Omron CX-Programmer project NuevoProyecto (CX-Programmer 9.50)

# PLC NewPLC1: CQM1 CPU21

## Program P20_1b2 (no task)
Local symbols
A 0.04 BOOL  ; Selección tolva A
B 0.05 BOOL  ; Selección tolva B
De 0.07 BOOL  ; Selección CIN3 derecha
EVA 100.04 BOOL  ; Electroválvula tolva A
EVB 100.05 BOOL  ; Electroválvula tolva B
Em 15.00 BOOL  ; Emergencia memorizada
Etapa_0 10.00 BOOL
Etapa_1 10.01 BOOL
Etapa_10 10.08 BOOL
Etapa_11 10.09 BOOL
Etapa_12 10.10 BOOL
Etapa_13 10.11 BOOL
Etapa_14 10.12 BOOL
Etapa_2 10.02 BOOL
Etapa_3 10.03 BOOL
Etapa_4 10.04 BOOL
Etapa_5 10.05 BOOL
Etapa_6 10.06 BOOL
Etapa_7 10.07 BOOL
FS_Etapa_12 15.07 BOOL  ; Flanco de subida Etapa_12
FS_Etapa_2 15.03 BOOL  ; Flanco de subida Etapa_2
FS_Etapa_3 15.04 BOOL  ; Flanco de subida Etapa_3
FS_Etapa_6 15.05 BOOL  ; Flanco de subida Etapa_6
FS_Etapa_7 15.06 BOOL  ; Flanco de subida Etapa_7
H_1 100.06 BOOL  ; Lámpara marcha
H_2 100.07 BOOL  ; Lámpara paro
H_3 101.00 BOOL  ; Lámpara emergencia
H_4 101.01 BOOL  ; Lámpara RT1
H_5 101.02 BOOL  ; Lámpara RT2
H_6 101.03 BOOL  ; Lámpara RT3
Iz 0.06 BOOL  ; Selección CIN3 izquierda
K1 100.00 BOOL  ; Contactor CIN1
K2 100.01 BOOL  ; Contactor CIN2
K3D 100.03 BOOL  ; Contactor derecha CIN3
K3I 100.02 BOOL  ; Contactor izquierda CIN3
PE 0.02 BOOL  ; Pulsador de emergencia
PM 0.00 BOOL  ; Pulsador de marcha
PP 0.01 BOOL  ; Pulsador de paro
PR 0.03 BOOL  ; Pulsador de rearme
RT 15.01 BOOL  ; RT=RT1+RT2+RT3
RT1 0.08 BOOL  ; Relé térmico CIN1
RT2 0.09 BOOL  ; Relé térmico CIN2
RT3 0.10 BOOL  ; Relé térmico CIN3
RTm 15.02 BOOL  ; Relés térmicos memorizados
T_0 15.03 BOOL  ; Variable auxiliar T_0

### Section Sección1_Programa_principal
; Etapas 0 ... 7

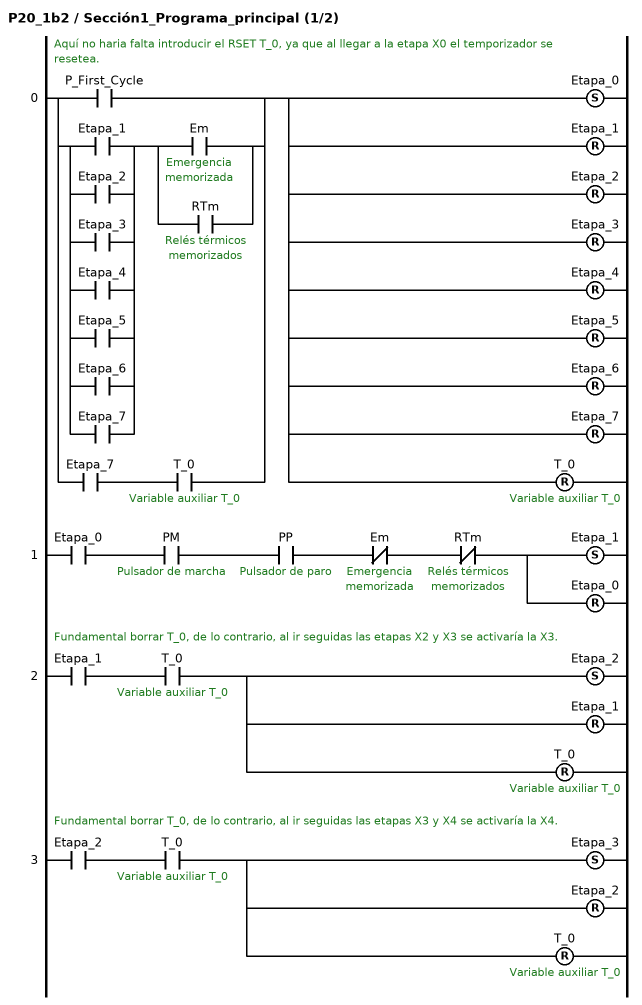
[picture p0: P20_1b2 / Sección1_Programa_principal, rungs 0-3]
; rung 0: Aquí no haria falta introducir el RSET T_0, ya que al llegar a la etapa X0 el temporizador se resetea.
LD P_First_Cycle
LD Etapa_1
OR Etapa_2
OR Etapa_3
OR Etapa_4
OR Etapa_5
OR Etapa_6
OR Etapa_7
LD Em  ; Emergencia memorizada
OR RTm  ; Relés térmicos memorizados
ANDLD
ORLD
LD Etapa_7
AND T_0  ; Variable auxiliar T_0
ORLD
SET Etapa_0
RSET Etapa_1
RSET Etapa_2
RSET Etapa_3
RSET Etapa_4
RSET Etapa_5
RSET Etapa_6
RSET Etapa_7
RSET T_0  ; Variable auxiliar T_0  // Como norma general se reseteará la variable auxiliar T_0 nada más haya cumplido su cometido.
; rung 1
LD Etapa_0
AND PM  ; Pulsador de marcha
AND PP  ; Pulsador de paro
ANDNOT Em  ; Emergencia memorizada
ANDNOT RTm  ; Relés térmicos memorizados
SET Etapa_1
RSET Etapa_0
; rung 2: Fundamental borrar T_0, de lo contrario, al ir seguidas las etapas X2 y X3 se activaría la X3.
LD Etapa_1
AND T_0  ; Variable auxiliar T_0
SET Etapa_2
RSET Etapa_1
RSET T_0  ; Variable auxiliar T_0  // Como norma general se reseteará la variable auxiliar T_0 nada más haya cumplido su cometido.
; rung 3: Fundamental borrar T_0, de lo contrario, al ir seguidas las etapas X3 y X4 se activaría la X4.
LD Etapa_2
AND T_0  ; Variable auxiliar T_0
SET Etapa_3
RSET Etapa_2
RSET T_0  ; Variable auxiliar T_0  // Como norma general se reseteará la variable auxiliar T_0 nada más haya cumplido su cometido.

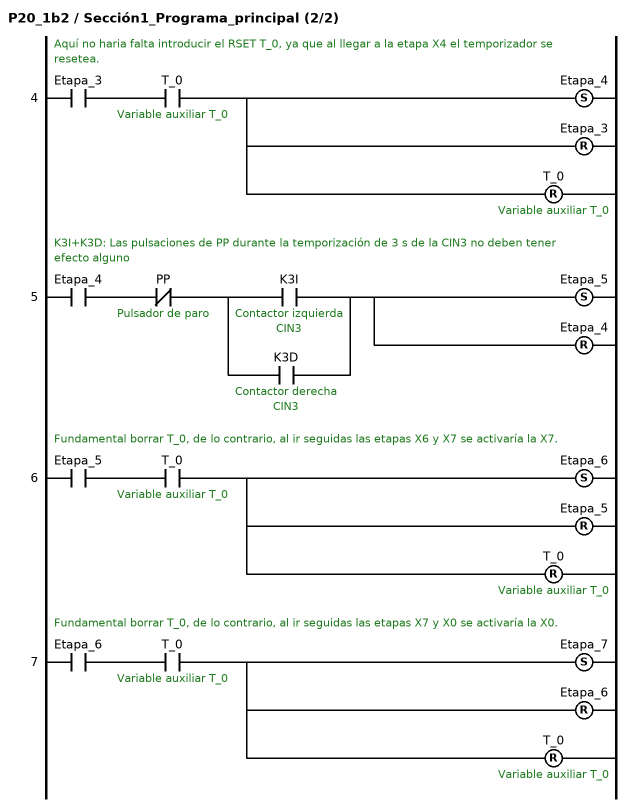
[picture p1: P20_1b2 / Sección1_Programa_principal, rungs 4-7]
; rung 4: Aquí no haria falta introducir el RSET T_0, ya que al llegar a la etapa X4 el temporizador se resetea.
LD Etapa_3
AND T_0  ; Variable auxiliar T_0
SET Etapa_4
RSET Etapa_3
RSET T_0  ; Variable auxiliar T_0  // Como norma general se reseteará la variable auxiliar T_0 nada más haya cumplido su cometido.
; rung 5: K3I+K3D: Las pulsaciones de PP durante la temporización de 3 s de la CIN3 no deben tener efecto alguno
LD Etapa_4
ANDNOT PP  ; Pulsador de paro
LD K3I  ; Contactor izquierda CIN3
OR K3D  ; Contactor derecha CIN3
ANDLD
SET Etapa_5
RSET Etapa_4
; rung 6: Fundamental borrar T_0, de lo contrario, al ir seguidas las etapas X6 y X7 se activaría la X7.
LD Etapa_5
AND T_0  ; Variable auxiliar T_0
SET Etapa_6
RSET Etapa_5
RSET T_0  ; Variable auxiliar T_0
; rung 7: Fundamental borrar T_0, de lo contrario, al ir seguidas las etapas X7 y X0 se activaría la X0.
LD Etapa_6
AND T_0  ; Variable auxiliar T_0
SET Etapa_7
RSET Etapa_6
RSET T_0  ; Variable auxiliar T_0

### Section Sección2_Disparo_térmicos
; Etapas 10 ... 14

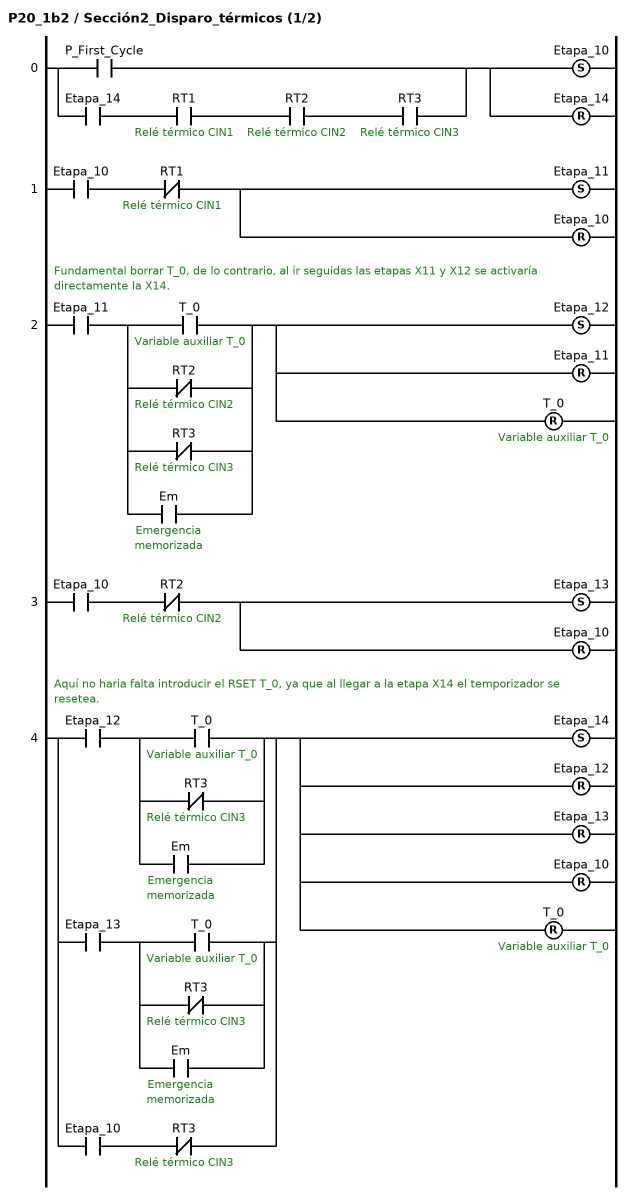
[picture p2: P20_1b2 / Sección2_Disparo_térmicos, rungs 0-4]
; rung 0
LD P_First_Cycle
LD Etapa_14
AND RT1  ; Relé térmico CIN1
AND RT2  ; Relé térmico CIN2
AND RT3  ; Relé térmico CIN3
ORLD
SET Etapa_10
RSET Etapa_14
; rung 1
LD Etapa_10
ANDNOT RT1  ; Relé térmico CIN1
SET Etapa_11
RSET Etapa_10
; rung 2: Fundamental borrar T_0, de lo contrario, al ir seguidas las etapas X11 y X12 se activaría directamente la X14.
LD Etapa_11
LD T_0  ; Variable auxiliar T_0
ORNOT RT2  ; Relé térmico CIN2
ORNOT RT3  ; Relé térmico CIN3
OR Em  ; Emergencia memorizada
ANDLD
SET Etapa_12
RSET Etapa_11
RSET T_0  ; Variable auxiliar T_0
; rung 3
LD Etapa_10
ANDNOT RT2  ; Relé térmico CIN2
SET Etapa_13
RSET Etapa_10
; rung 4: Aquí no haria falta introducir el RSET T_0, ya que al llegar a la etapa X14 el temporizador se resetea.
LD Etapa_12
LD T_0  ; Variable auxiliar T_0
ORNOT RT3  ; Relé térmico CIN3
OR Em  ; Emergencia memorizada
ANDLD
LD Etapa_13
LD T_0  ; Variable auxiliar T_0
ORNOT RT3  ; Relé térmico CIN3
OR Em  ; Emergencia memorizada
ANDLD
ORLD
LD Etapa_10
ANDNOT RT3  ; Relé térmico CIN3
ORLD
SET Etapa_14
RSET Etapa_12
RSET Etapa_13
RSET Etapa_10
RSET T_0  ; Variable auxiliar T_0  // Como norma general se reseteará la variable auxiliar T_0 nada más haya cumplido su cometido.

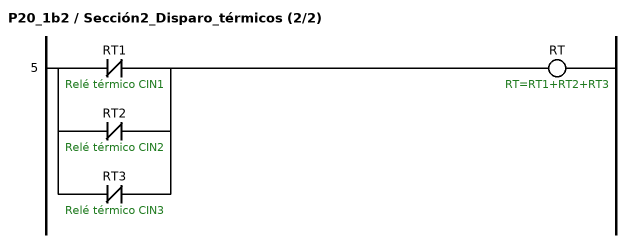
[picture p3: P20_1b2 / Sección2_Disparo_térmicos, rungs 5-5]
; rung 5
LDNOT RT1  ; Relé térmico CIN1
ORNOT RT2  ; Relé térmico CIN2
ORNOT RT3  ; Relé térmico CIN3
OUT RT  ; RT=RT1+RT2+RT3

### Section Sección3_Temporizadores

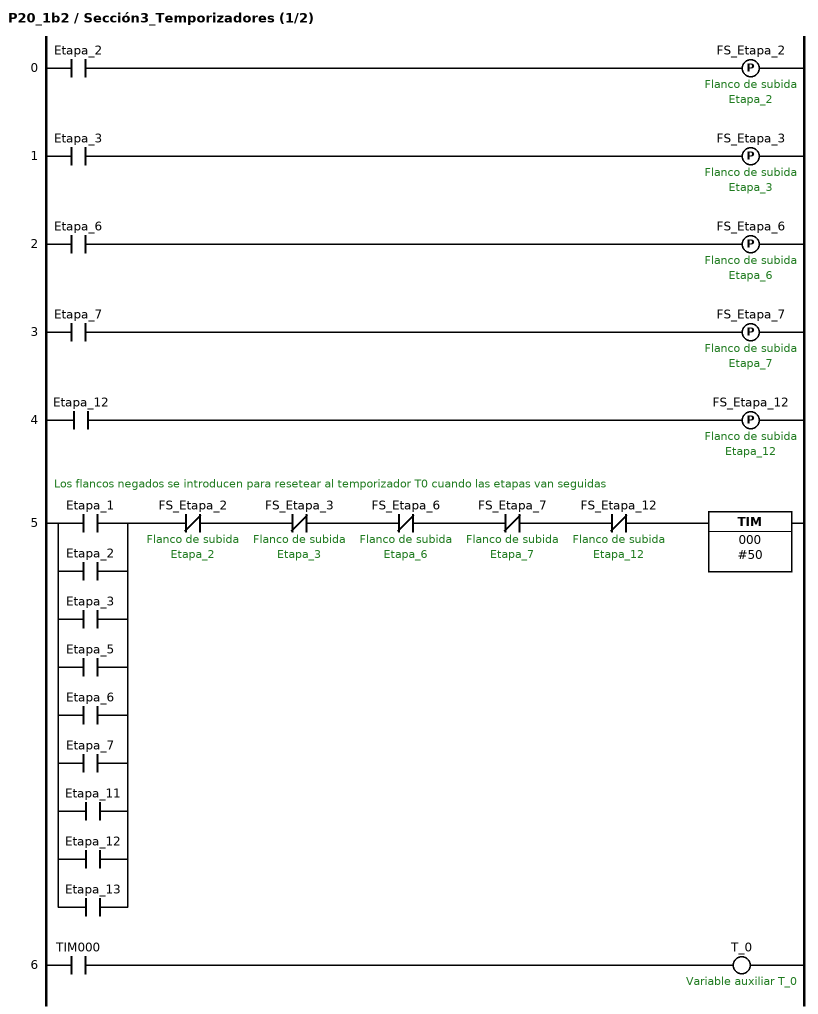
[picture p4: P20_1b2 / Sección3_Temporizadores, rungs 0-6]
; rung 0
LD Etapa_2
DIFU(13) FS_Etapa_2  ; Flanco de subida Etapa_2
; rung 1
LD Etapa_3
DIFU(13) FS_Etapa_3  ; Flanco de subida Etapa_3
; rung 2
LD Etapa_6
DIFU(13) FS_Etapa_6  ; Flanco de subida Etapa_6
; rung 3
LD Etapa_7
DIFU(13) FS_Etapa_7  ; Flanco de subida Etapa_7
; rung 4
LD Etapa_12
DIFU(13) FS_Etapa_12  ; Flanco de subida Etapa_12
; rung 5: Los flancos negados se introducen para resetear al temporizador T0 cuando las etapas van seguidas
LD Etapa_1
OR Etapa_2
OR Etapa_3
OR Etapa_5
OR Etapa_6
OR Etapa_7
OR Etapa_11
OR Etapa_12
OR Etapa_13
ANDNOT FS_Etapa_2  ; Flanco de subida Etapa_2
ANDNOT FS_Etapa_3  ; Flanco de subida Etapa_3
ANDNOT FS_Etapa_6  ; Flanco de subida Etapa_6
ANDNOT FS_Etapa_7  ; Flanco de subida Etapa_7
ANDNOT FS_Etapa_12  ; Flanco de subida Etapa_12
TIM 000 #50
; rung 6
LD TIM000
OUT T_0  ; Variable auxiliar T_0

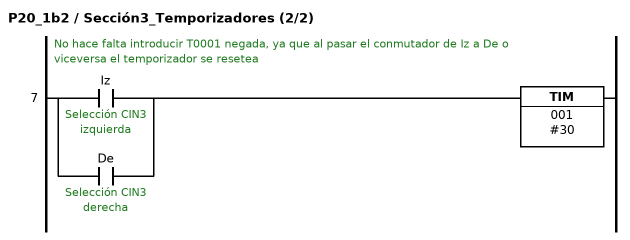
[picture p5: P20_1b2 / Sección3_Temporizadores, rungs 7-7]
; rung 7: No hace falta introducir T0001 negada, ya que al pasar el conmutador de Iz a De o viceversa el temporizador se resetea
LD Iz  ; Selección CIN3 izquierda
OR De  ; Selección CIN3 derecha
TIM 001 #30

### Section Sección4_Memorizaciones

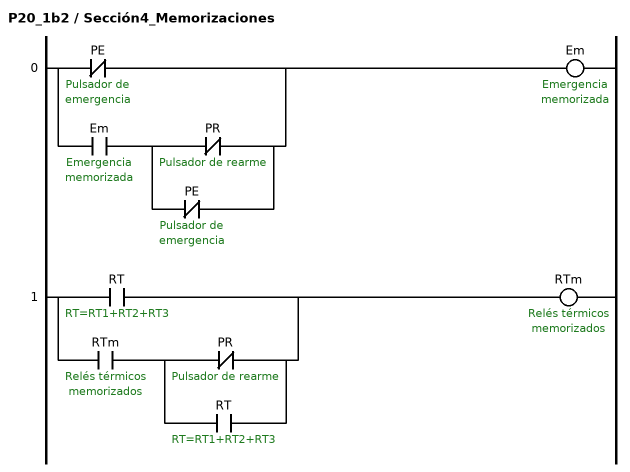
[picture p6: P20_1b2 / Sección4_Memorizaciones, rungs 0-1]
; rung 0
LDNOT PE  ; Pulsador de emergencia
LD Em  ; Emergencia memorizada
LDNOT PR  ; Pulsador de rearme
ORNOT PE  ; Pulsador de emergencia
ANDLD
ORLD
OUT Em  ; Emergencia memorizada
; rung 1
LD RT  ; RT=RT1+RT2+RT3
LD RTm  ; Relés térmicos memorizados
LDNOT PR  ; Pulsador de rearme
OR RT  ; RT=RT1+RT2+RT3
ANDLD
ORLD
OUT RTm  ; Relés térmicos memorizados

### Section Sección5_Salidas

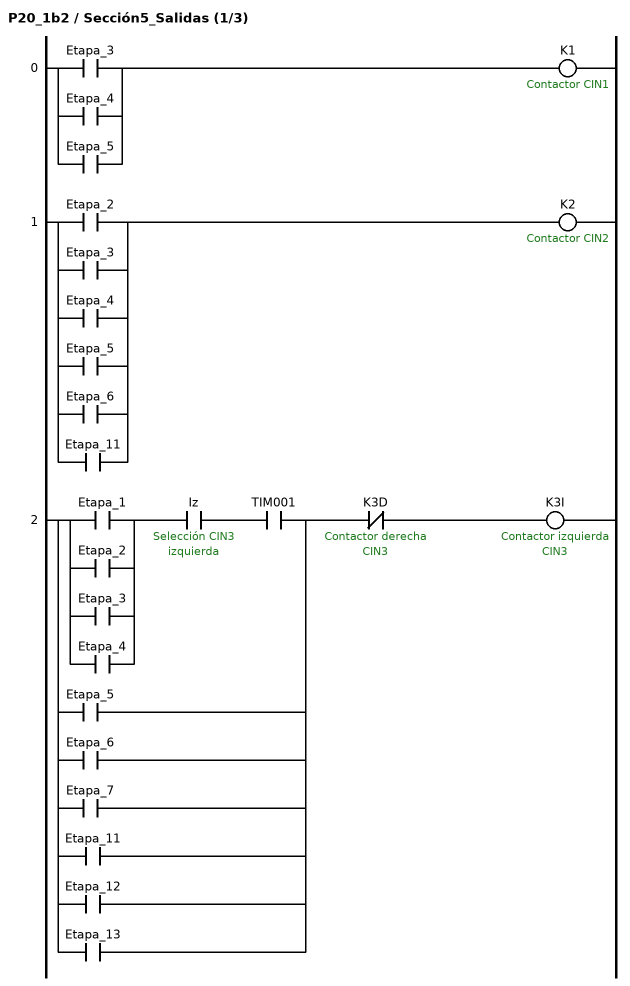
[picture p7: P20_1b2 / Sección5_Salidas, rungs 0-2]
; rung 0
LD Etapa_3
OR Etapa_4
OR Etapa_5
OUT K1  ; Contactor CIN1
; rung 1
LD Etapa_2
OR Etapa_3
OR Etapa_4
OR Etapa_5
OR Etapa_6
OR Etapa_11
OUT K2  ; Contactor CIN2
; rung 2
LD Etapa_1
OR Etapa_2
OR Etapa_3
OR Etapa_4
AND Iz  ; Selección CIN3 izquierda
AND TIM001
OR Etapa_5
OR Etapa_6
OR Etapa_7
OR Etapa_11
OR Etapa_12
OR Etapa_13
ANDNOT K3D  ; Contactor derecha CIN3
OUT K3I  ; Contactor izquierda CIN3

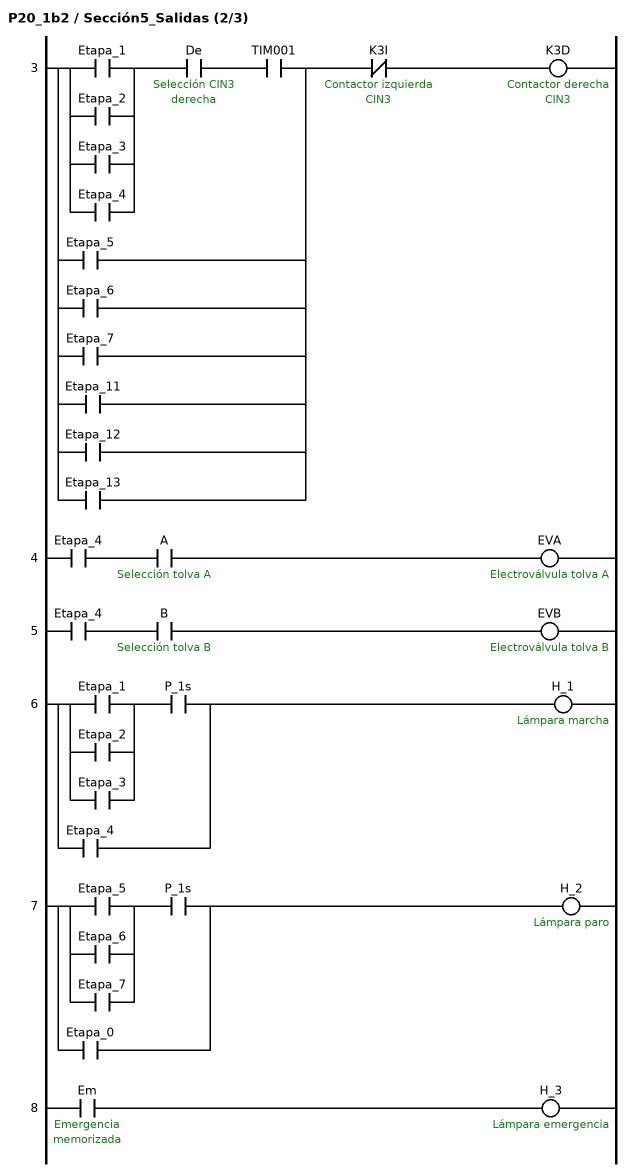
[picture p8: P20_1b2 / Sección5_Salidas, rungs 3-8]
; rung 3
LD Etapa_1
OR Etapa_2
OR Etapa_3
OR Etapa_4
AND De  ; Selección CIN3 derecha
AND TIM001
OR Etapa_5
OR Etapa_6
OR Etapa_7
OR Etapa_11
OR Etapa_12
OR Etapa_13
ANDNOT K3I  ; Contactor izquierda CIN3
OUT K3D  ; Contactor derecha CIN3
; rung 4
LD Etapa_4
AND A  ; Selección tolva A
OUT EVA  ; Electroválvula tolva A
; rung 5
LD Etapa_4
AND B  ; Selección tolva B
OUT EVB  ; Electroválvula tolva B
; rung 6
LD Etapa_1
OR Etapa_2
OR Etapa_3
AND P_1s
OR Etapa_4
OUT H_1  ; Lámpara marcha
; rung 7
LD Etapa_5
OR Etapa_6
OR Etapa_7
AND P_1s
OR Etapa_0
OUT H_2  ; Lámpara paro
; rung 8
LD Em  ; Emergencia memorizada
OUT H_3  ; Lámpara emergencia

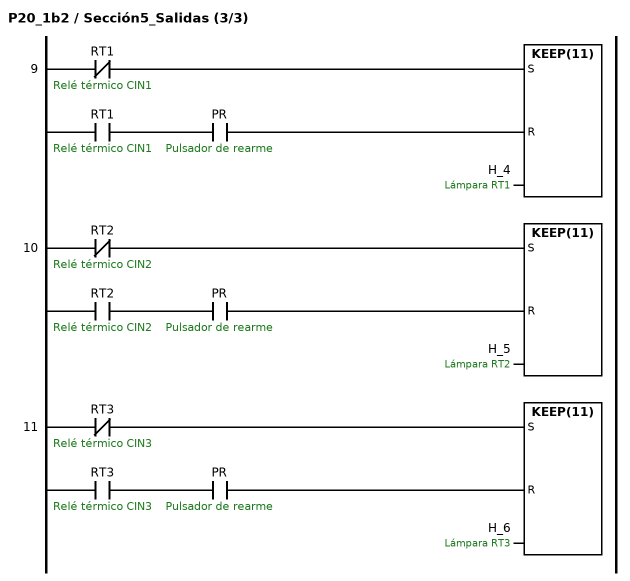
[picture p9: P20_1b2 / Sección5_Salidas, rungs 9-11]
; rung 9
LDNOT RT1  ; Relé térmico CIN1
LD RT1  ; Relé térmico CIN1
AND PR  ; Pulsador de rearme
KEEP(11) H_4  ; Lámpara RT1
; rung 10
LDNOT RT2  ; Relé térmico CIN2
LD RT2  ; Relé térmico CIN2
AND PR  ; Pulsador de rearme
KEEP(11) H_5  ; Lámpara RT2
; rung 11
LDNOT RT3  ; Relé térmico CIN3
LD RT3  ; Relé térmico CIN3
AND PR  ; Pulsador de rearme
KEEP(11) H_6  ; Lámpara RT3

### Section Sección6_END
; rung 0: Fin de programa
END(01)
